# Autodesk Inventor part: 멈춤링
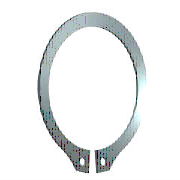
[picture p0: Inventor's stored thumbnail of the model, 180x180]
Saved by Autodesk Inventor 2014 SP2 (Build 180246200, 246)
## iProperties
IsCustomPart: 1
Company: 한국ATC센터
Created: 2014-10
Part Number: 멈춤링
Material: 강철, 연강
Description: 리테이닝 링(C형)
Document SubType Name: Modeling
Standard: KS B 1336
Designer: 한국ATC센터
Standards Organization: KS
Language: ko-KR
Size Designation: 25 x 1.2
Categories: <MemberInstance><Categories><Category DisplayName="샤프트 부품" InternalName="7f7aeb1f-a693-4053-b835-cee3144e0d98" Mnemonic="SHFT"><Category DisplayName="써클립" Inter
Density: 7.86 g/cm^3
Mass: 2.3429 g
Surface Area: 7.2498 cm^2
Volume: 0.298079 cm^3
Appearance: 강철
Author: KYOUNG IL JANG
Revision Number: 1
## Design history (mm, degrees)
sketch "스케치1"
  geometry: L1 (-6, 0)-(6, 0) reference; L2 (0, 20.189)-(0, -80.536) reference; L3 (-48.09, 0)-(48.09, 0) reference; L4 (-0.5, -24.44)-(-0.5, -28.74); L5 (-0.5, -6.54)-(-0.5, -13.29); L6 (-2.795, 3.1)-(3.672, 3.1); L7 (0.5, -6.54)-(0.5, -13.29); L8 (0.5, -24.44)-(0.5, -28.74); C1 r 1 at (-2, -26.606); C2 r 1 at (2, -26.606); A1 r 11.95 centre (0, -12.5) between (0.5, -24.44) and (-0.5, -24.44); A2 r 14.825 centre (0, -11.725) between (5.202, -25.608) and (-5.202, -25.608); A3 r 16.247 centre (0, -12.5) between (-2.281, -28.586) and (-0.5, -28.74); A4 r 2 centre (-2, -26.606) between (-3.952, -27.043) and (-2.281, -28.586); A5 r 2 centre (-5.903, -27.48) between (-3.952, -27.043) and (-5.202, -25.608); A6 r 2 centre (5.903, -27.48) between (5.202, -25.608) and (3.952, -27.043); A7 r 2 centre (2, -26.606) between (2.281, -28.586) and (3.952, -27.043); A8 r 16.247 centre (0, -12.5) between (0.5, -28.74) and (2.281, -28.586)
  constraints: 16 point on circle, 12 end point, 10 centre point, 9 symmetric about line, 5 point on line, 4 tangent, 3 coincident, 2 horizontal, 1 perpendicular, 1 vertical, 5 other
  dimensions: "d0" = 23.9 diameter of A1 (= ND); "d1" = 4.3 distance of L4.end L4.start (= SRB2); "d6" = 0.5 distance between parallel lines of L2 L5 (= 0.25 x SD5); "d7" = 3.1 distance between parallel lines of L6 L3 (= SRB1); "d8" = 0.775 distance of A1.centre A2.centre (= 0.25 x SRB1); "d9" = 2 radius of A4 (= SD5); "d10" = 2 radius of A5 (= SD5); "d11" = 1.5 distance from line of L4 A4.centre (= 0.75 x SD5); "d12" = 2 diameter of C1 (= SD5); "d13" = 2 diameter of C2 (= SD5); "d14" = 12.5 distance from line of A1.centre L1 (= 0.5 x WD)
extrude "본체" new body sketch "스케치1" distance "d2" = 1.2 (= SD); taper "d3" = 0 deg
workaxis "Work Axis1"
workplane "Work Plane1"
body "Solid1"
other parameters: "WD" = 25 (= WDMIN) [user parameter; used in 1 equation term], "SD" = 1.2 [user parameter; used in 1 equation term], "SRB1" = 3.1 [user parameter; used in 2 equation terms], "ND" = 23.9 [user parameter; used in 1 equation term], "SRB2" = 4.3 [user parameter; used in 1 equation term], "SD5" = 2 [user parameter; used in 6 equation terms], "d15" = 0, "d16" = 0, "d17" = 0, "d41" = 0, "d42" = 0, "WDMIN" = 25 [user parameter; used in 1 equation term], "SD3" = 23.2 [user parameter], "WDMAX" = 26 [user parameter]
